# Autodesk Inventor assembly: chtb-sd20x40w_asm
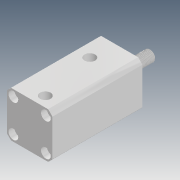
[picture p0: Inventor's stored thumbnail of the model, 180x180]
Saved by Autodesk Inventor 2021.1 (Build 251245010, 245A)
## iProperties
Company: Microsoft
Created: 2018-05
Part Number: chtb-sd20x40w_asm
Description: STEP AP214
Document SubType Name: Assembly
Designer: user
Title: chtb-sd20x40w_asm.STEP
Author: Windows
Revision Number: ÈÎºÎ
Sending System: SolidWorks 2015
Preprocessor: SwSTEP 2.0
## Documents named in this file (4)
- D:\Vault_2016\Projekty\Clamptek\Hydraulic\CHTB\CHTB-20\Inventor\CHTB-SD20x40W\chtb-sd20x40w_asm.iam
- D:\Vault_2016\Projekty\Clamptek\Hydraulic\CHTB\CHTB-20\Inventor\CHTB-SD20x40W\CHTB-SD20X40NBT.ipt
- D:\Vault_2016\Projekty\Clamptek\Hydraulic\CHTB\CHTB-20\Inventor\CHTB-SD20x40W\CHTB-SD20X40WHSG.ipt
- D:\Vault_2016\Projekty\Clamptek\Hydraulic\CHTB\CHTB-20\Inventor\CHTB-SD20x40W\QG.ipt
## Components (3 placed, 3 different names)
1. CHTB-SD20X40NBT_1
2. CHTB-SD20X40WHSG_2
3. QG_3
